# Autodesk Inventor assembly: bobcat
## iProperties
Author: vincent molino
Shininess: 64.0
Angle Display Precision: 2
Document Length Units: 11272
Document Angle Units: 11286
Document Time Units: 11279
Document Mass Units: 11290
Document Length Units Precision: 3
Document Angle Units Precision: 2
Compacted: True
PropertySet Name: _Private Model Information
Created: 2002-01
Part Number: bobcat
Document SubType Name: Assembly
Designer: vincent molino
Control State: 0
Master: False
Checked Out: False
PropertySet Name: Design Tracking Control
Density: 0.0
Volumn: 0.0
Area: 0.0
PropertySet Name: Model Information
